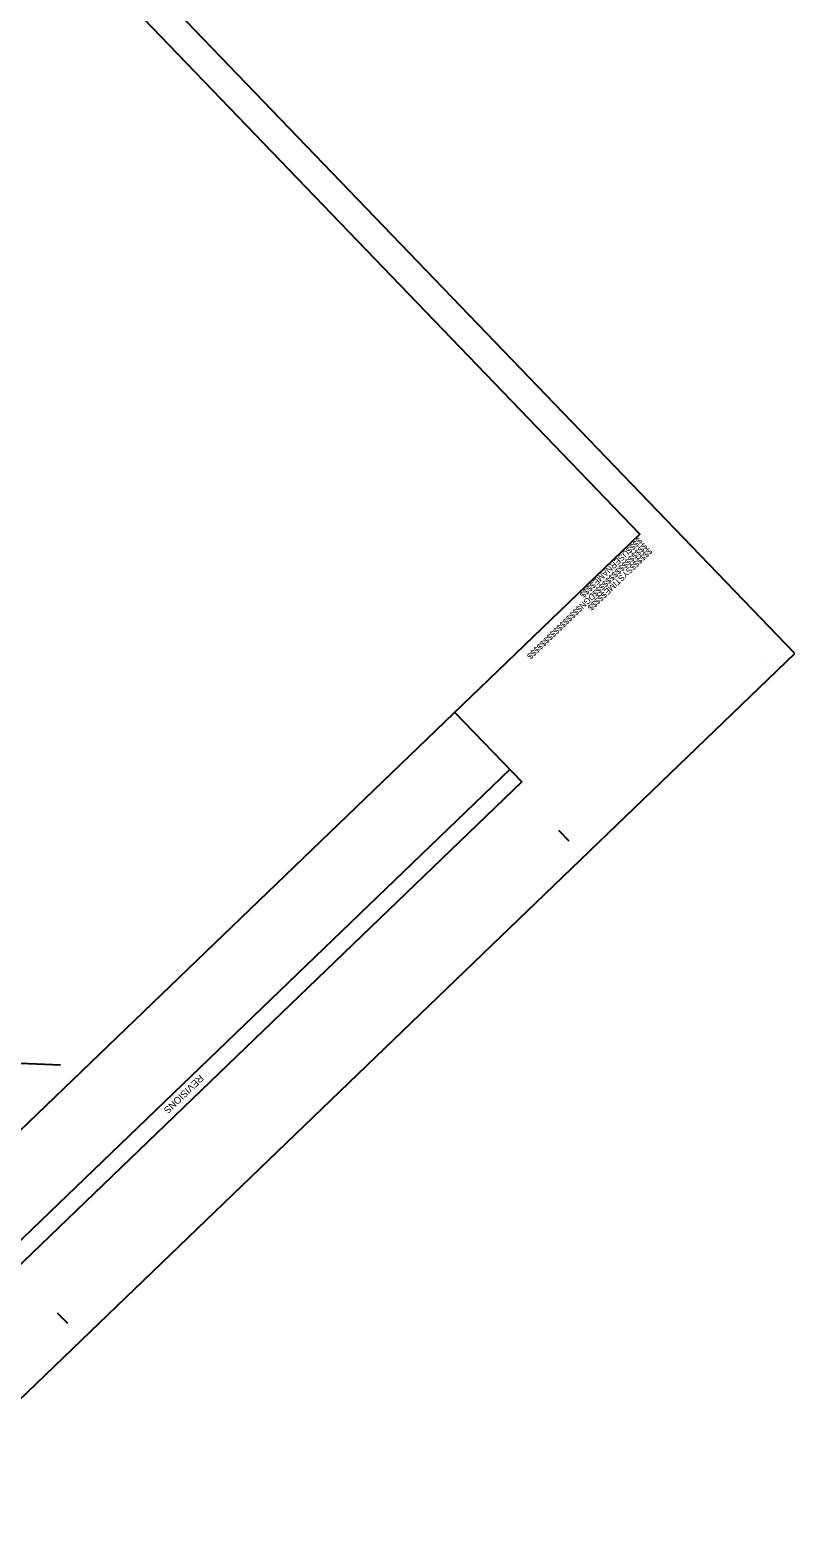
# Model space of a CAD drawing. Extents: x 471894 to 476235, y 503501 to 507878.
# Drawn here: x 474775 to 476235, y 503501 to 506381 of the extents above; entities that cross this region are included whole.
import ezdxf

# ---------------------------------------------------------------- set-up
doc = ezdxf.new("R2010")
doc.units = 0
for name, color, linetype in [('CTL Sheet Border CELL', 7, 'Continuous'), ('Matchline', 7, 'Continuous'), ('Sheet Block Revision CELL', 7, 'Continuous'), ('Sheet Plot Border Outside CELL', 7, 'Continuous')]:
    doc.layers.add(name, color=color, linetype=linetype)

msp = doc.modelspace()

# ---------------------------------------------------------------- linework, layer by layer
at = {"layer": 'CTL Sheet Border CELL'}
for p, q in [((475939, 505418.6), (475939, 505418.6)), ((475939, 505418.6), (475939, 505418.6)), ((475939, 505418.6), (475939, 505418.6)), ((475939, 505418.6), (475939, 505418.6)), ((475939, 505418.6), (475939, 505418.6)), ((475939, 505418.6), (475939, 505418.6)), ((475939, 505418.6), (475939, 505418.6)), ((475939, 505418.6), (475939, 505418.6)), ((475939, 505418.6), (475939, 505418.6)), ((475939, 505418.6), (475939, 505418.6)), ((475939, 505418.6), (475939, 505418.6)), ((476235.3, 505190.5), (476235.3, 505190.5)), ((476179.6, 505176.8), (476179.6, 505176.8)), ((475804, 504832.3), (475784.8, 504852.2)), ((474846.5, 503910.9), (474827.3, 503930.8))]:
    msp.add_line(p, q, dxfattribs=at)
msp.add_lwpolyline([(471960, 506200), (474263.4, 503806.2), (475939, 505418.6), (473635.6, 507812.3)], close=True, dxfattribs=at)
msp.add_lwpolyline([(475881.4, 505478.5), (475881.4, 505478.5)], dxfattribs=at)
msp.add_lwpolyline([(475881.4, 505478.5), (475881.4, 505478.5)], dxfattribs=at)
at = {"layer": 'Matchline'}
msp.add_line((474348.8, 504424.8), (474832.8, 504404.9), dxfattribs=at)
at = {"layer": 'Sheet Block Revision CELL'}
for p, q in [((475585.5, 505078.4), (475713.8, 504945.2)), ((475690.8, 504969.1), (474429.4, 503755.3)), ((475713.8, 504945.2), (474452.4, 503731.4))]:
    msp.add_line(p, q, dxfattribs=at)
at = {"layer": 'Sheet Plot Border Outside CELL'}
msp.add_lwpolyline([(476235.3, 505190.5), (473649.4, 507877.9), (471894, 506188.7), (474479.9, 503501.3)], close=True, dxfattribs=at)

# ---------------------------------------------------------------- texts
at = {"layer": 'CTL Sheet Border CELL'}
for s, p in [('$$$$USERNAME$$$$', (475936.9, 505413.3)), ('$$$$$$$$$$$$$$$$DGN$$$$$$$$$$$$$$$$', (475947, 505402.8)), ('$$$$$$SYSTIME$$$$$', (475956.3, 505393.1))]:
    msp.add_text(s, height=11.627, rotation=223.8985, dxfattribs=at).set_placement(p)
at = {"layer": 'Sheet Block Revision CELL'}
msp.add_text('REVISIONS', height=13.28, rotation=223.8985, dxfattribs=at).set_placement((475098.6, 504387.1))

doc.saveas('drawing.dxf')
